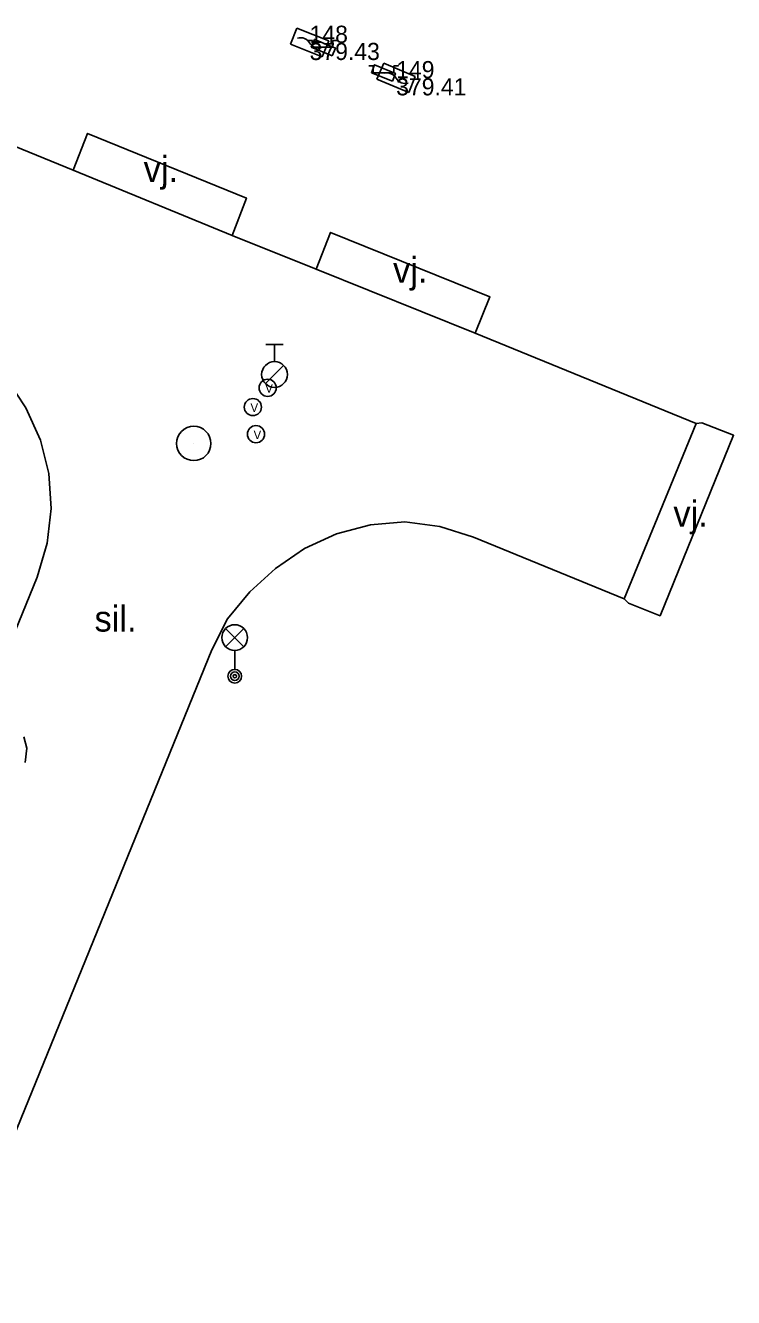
# Model space of a CAD drawing. Extents: x -836568 to -836015, y -1070547 to -1070212.
# Drawn here: x -836394 to -836373.39, y -1070376.08 to -1070339.02 of the extents above; entities that cross this region are included whole.
import ezdxf

# ---------------------------------------------------------------- set-up
doc = ezdxf.new("R2010")
doc.units = 0
for name, color, linetype in [('BodPole_mer', 7, 'Continuous'), ('BodPole_popis', 7, 'Continuous'), ('Doprava_hranice', 7, 'Continuous'), ('Doprava_kody', 7, 'Continuous'), ('PovrZnIS_body', 7, 'Continuous'), ('PovrZnIS_hranice', 7, 'Continuous'), ('PovrZnIS_kody', 7, 'Continuous')]:
    doc.layers.add(name, color=color, linetype=linetype)

msp = doc.modelspace()

# ---------------------------------------------------------------- linework, layer by layer
at = {"layer": 'BodPole_mer'}
for p, q in [((-836385.73, -1070339.53), (-836385.73, -1070339.53)), ((-836385.59, -1070339.43), (-836385.59, -1070339.43)), ((-836385.59, -1070339.43), (-836385.59, -1070339.43)), ((-836385.68, -1070339.66), (-836385.68, -1070339.66)), ((-836385.68, -1070339.66), (-836385.68, -1070339.66)), ((-836385.07, -1070339.91), (-836385.07, -1070339.91)), ((-836385.07, -1070339.91), (-836385.07, -1070339.91)), ((-836384.98, -1070339.68), (-836384.98, -1070339.68)), ((-836384.98, -1070339.68), (-836384.98, -1070339.68)), ((-836383.84, -1070340.17), (-836383.84, -1070340.17)), ((-836383.84, -1070340.17), (-836383.84, -1070340.17)), ((-836383.93, -1070340.4), (-836383.93, -1070340.4)), ((-836383.93, -1070340.4), (-836383.93, -1070340.4)), ((-836383.32, -1070340.65), (-836383.32, -1070340.65)), ((-836383.32, -1070340.65), (-836383.32, -1070340.65)), ((-836383.23, -1070340.42), (-836383.23, -1070340.42)), ((-836383.23, -1070340.42), (-836383.23, -1070340.42)), ((-836383.21, -1070340.56), (-836383.21, -1070340.56)), ((-836392.19, -1070342.17), (-836392.19, -1070342.17)), ((-836392.61, -1070343.24), (-836392.61, -1070343.24)), ((-836387.57, -1070344.05), (-836387.57, -1070344.05)), ((-836387.98, -1070345.14), (-836387.98, -1070345.14)), ((-836385.12, -1070345.05), (-836385.12, -1070345.05)), ((-836385.54, -1070346.12), (-836385.54, -1070346.12)), ((-836380.48, -1070346.93), (-836380.48, -1070346.93)), ((-836380.91, -1070347.99), (-836380.91, -1070347.99)), ((-836386.75, -1070349.19), (-836386.75, -1070349.19)), ((-836386.95, -1070349.58), (-836386.95, -1070349.58)), ((-836393.99, -1070350.16), (-836393.99, -1070350.16)), ((-836387.38, -1070350.14), (-836387.38, -1070350.14)), ((-836374.48, -1070350.62), (-836374.48, -1070350.62)), ((-836374.31, -1070350.6), (-836374.31, -1070350.6)), ((-836393.56, -1070351.1), (-836393.56, -1070351.1)), ((-836387.29, -1070350.93), (-836387.29, -1070350.93)), ((-836373.39, -1070350.96), (-836373.39, -1070350.96)), ((-836389.1, -1070351.2), (-836389.1, -1070351.2)), ((-836393.32, -1070352.07), (-836393.32, -1070352.07)), ((-836393.25, -1070353.09), (-836393.25, -1070353.09)), ((-836383.96, -1070353.57), (-836383.96, -1070353.57)), ((-836382.96, -1070353.48), (-836382.96, -1070353.48)), ((-836381.94, -1070353.62), (-836381.94, -1070353.62)), ((-836393.37, -1070354.1), (-836393.37, -1070354.1)), ((-836384.95, -1070353.83), (-836384.95, -1070353.83)), ((-836380.96, -1070353.93), (-836380.96, -1070353.93)), ((-836385.88, -1070354.26), (-836385.88, -1070354.26)), ((-836386.72, -1070354.84), (-836386.72, -1070354.84)), ((-836393.66, -1070355.09), (-836393.66, -1070355.09)), ((-836387.47, -1070355.52), (-836387.47, -1070355.52)), ((-836376.57, -1070355.73), (-836376.57, -1070355.73)), ((-836376.45, -1070355.85), (-836376.45, -1070355.85)), ((-836388.12, -1070356.31), (-836388.12, -1070356.31)), ((-836375.53, -1070356.22), (-836375.53, -1070356.22)), ((-836388.58, -1070357.21), (-836388.58, -1070357.21)), ((-836387.91, -1070357.98), (-836387.91, -1070357.98)), ((-836393.96, -1070360.08), (-836393.96, -1070360.08))]:
    msp.add_line(p, q, dxfattribs=at)
at = {"layer": 'Doprava_hranice'}
for points in [[(-836399.02, -1070340.62), (-836392.61, -1070343.24), (-836387.98, -1070345.14), (-836385.54, -1070346.12), (-836380.91, -1070347.99), (-836374.48, -1070350.62), (-836376.57, -1070355.73), (-836380.96, -1070353.93), (-836381.94, -1070353.62), (-836382.96, -1070353.48), (-836383.96, -1070353.57), (-836384.95, -1070353.83), (-836385.88, -1070354.26), (-836386.72, -1070354.84), (-836387.47, -1070355.52), (-836388.12, -1070356.31), (-836388.58, -1070357.21), (-836396.26, -1070376.08)], [(-836392.61, -1070343.24), (-836392.19, -1070342.17), (-836387.57, -1070344.05), (-836387.98, -1070345.14)], [(-836385.54, -1070346.12), (-836385.12, -1070345.05), (-836380.48, -1070346.93), (-836380.91, -1070347.99)], [(-836395.25, -1070358.98), (-836393.66, -1070355.09), (-836393.37, -1070354.1), (-836393.25, -1070353.09), (-836393.32, -1070352.07), (-836393.56, -1070351.1), (-836393.99, -1070350.16), (-836394.55, -1070349.31)], [(-836374.48, -1070350.62), (-836374.31, -1070350.6), (-836373.39, -1070350.96), (-836375.53, -1070356.22), (-836376.45, -1070355.85), (-836376.57, -1070355.73)], [(-836394.01, -1070360.49), (-836393.96, -1070360.08), (-836394.05, -1070359.75)]]:
    msp.add_lwpolyline(points, dxfattribs=at)
at = {"layer": 'PovrZnIS_body'}
for p, q in [((-836386.287, -1070339.564), (-836386.102, -1070339.099)), ((-836386.102, -1070339.099), (-836385.173, -1070339.471)), ((-836385.359, -1070339.935), (-836386.287, -1070339.564)), ((-836385.173, -1070339.471), (-836385.359, -1070339.935)), ((-836383.768, -1070340.583), (-836383.573, -1070340.122)), ((-836383.573, -1070340.122), (-836382.652, -1070340.511)), ((-836382.846, -1070340.972), (-836383.768, -1070340.583)), ((-836382.652, -1070340.511), (-836382.846, -1070340.972)), ((-836387, -1070348.315), (-836386.5, -1070348.315)), ((-836386.75, -1070348.315), (-836386.75, -1070348.815)), ((-836386.485, -1070348.925), (-836387.015, -1070349.455)), ((-836388.175, -1070357.12), (-836387.645, -1070356.59)), ((-836388.175, -1070356.59), (-836387.645, -1070357.12)), ((-836387.91, -1070357.78), (-836387.91, -1070357.23))]:
    msp.add_line(p, q, dxfattribs=at)
for points in [[(-836386.08, -1070339.39), (-836386.032, -1070339.381), (-836385.982, -1070339.38), (-836385.931, -1070339.387), (-836385.882, -1070339.402), (-836385.835, -1070339.425), (-836385.793, -1070339.455), (-836385.758, -1070339.491), (-836385.73, -1070339.53)], [(-836385.73, -1070339.53), (-836385.702, -1070339.569), (-836385.667, -1070339.604), (-836385.626, -1070339.634), (-836385.579, -1070339.658), (-836385.529, -1070339.673), (-836385.479, -1070339.68), (-836385.429, -1070339.678), (-836385.382, -1070339.669)], [(-836383.557, -1070340.413), (-836383.509, -1070340.406), (-836383.459, -1070340.405), (-836383.409, -1070340.413), (-836383.359, -1070340.429), (-836383.313, -1070340.453), (-836383.272, -1070340.484), (-836383.237, -1070340.52), (-836383.21, -1070340.56)], [(-836383.21, -1070340.56), (-836383.183, -1070340.599), (-836383.148, -1070340.636), (-836383.108, -1070340.666), (-836383.062, -1070340.69), (-836383.012, -1070340.707), (-836382.962, -1070340.714), (-836382.912, -1070340.714), (-836382.864, -1070340.706)]]:
    msp.add_lwpolyline(points, dxfattribs=at)
for centre, radius in [((-836386.75, -1070349.19), 0.375), ((-836386.95, -1070349.58), 0.25), ((-836387.38, -1070350.14), 0.25), ((-836389.1, -1070351.2), 0.5), ((-836387.29, -1070350.93), 0.25)]:
    msp.add_circle(centre, radius, dxfattribs=at)
for centre, major_axis in [((-836387.91, -1070356.855), (0.375, 0)), ((-836387.91, -1070357.98), (0.2, 0)), ((-836387.906, -1070357.98), (0.125, 0)), ((-836387.906, -1070357.98), (0.05, 0))]:
    msp.add_ellipse(centre, major_axis=major_axis, ratio=0.999998, dxfattribs=at)
at = {"layer": 'PovrZnIS_hranice'}
for p, q in [((-836385.68, -1070339.66), (-836385.07, -1070339.91)), ((-836385.68, -1070339.66), (-836385.07, -1070339.91)), ((-836383.93, -1070340.4), (-836383.32, -1070340.65)), ((-836383.93, -1070340.4), (-836383.32, -1070340.65))]:
    msp.add_line(p, q, dxfattribs=at)
for points in [[(-836385.68, -1070339.66), (-836385.59, -1070339.43), (-836384.98, -1070339.68), (-836385.07, -1070339.91)], [(-836385.68, -1070339.66), (-836385.59, -1070339.43), (-836384.98, -1070339.68), (-836385.07, -1070339.91)], [(-836383.93, -1070340.4), (-836383.84, -1070340.17), (-836383.23, -1070340.42), (-836383.32, -1070340.65)], [(-836383.93, -1070340.4), (-836383.84, -1070340.17), (-836383.23, -1070340.42), (-836383.32, -1070340.65)]]:
    msp.add_lwpolyline(points, dxfattribs=at)
at = {"layer": 'PovrZnIS_kody'}
for p, q in [((-836385.771, -1070339.46), (-836385.65, -1070339.46)), ((-836385.771, -1070339.46), (-836385.65, -1070339.46)), ((-836385.65, -1070339.46), (-836385.65, -1070339.66)), ((-836385.65, -1070339.46), (-836385.65, -1070339.66)), ((-836385.05, -1070339.66), (-836385.05, -1070339.46)), ((-836385.05, -1070339.46), (-836384.916, -1070339.46)), ((-836385.05, -1070339.66), (-836385.05, -1070339.46)), ((-836385.05, -1070339.46), (-836384.916, -1070339.46)), ((-836385.65, -1070339.66), (-836385.05, -1070339.66)), ((-836385.65, -1070339.66), (-836385.05, -1070339.66)), ((-836384.001, -1070340.2), (-836383.88, -1070340.2)), ((-836384.001, -1070340.2), (-836383.88, -1070340.2)), ((-836383.88, -1070340.2), (-836383.88, -1070340.4)), ((-836383.88, -1070340.2), (-836383.88, -1070340.4)), ((-836383.28, -1070340.4), (-836383.28, -1070340.2)), ((-836383.28, -1070340.2), (-836383.146, -1070340.2)), ((-836383.28, -1070340.4), (-836383.28, -1070340.2)), ((-836383.28, -1070340.2), (-836383.146, -1070340.2)), ((-836383.88, -1070340.4), (-836383.28, -1070340.4)), ((-836383.88, -1070340.4), (-836383.28, -1070340.4))]:
    msp.add_line(p, q, dxfattribs=at)

# ---------------------------------------------------------------- texts
at = {"layer": 'BodPole_popis'}
for s, p in [('148', (-836385.73, -1070339.53)), ('379.43', (-836385.73, -1070340.03)), ('149', (-836383.21, -1070340.56)), ('379.41', (-836383.21, -1070341.06))]:
    msp.add_text(s, height=0.5, dxfattribs=at).set_placement(p)
at = {"layer": 'Doprava_kody'}
for s, p in [('vj.', (-836390.56, -1070343.58)), ('vj.', (-836383.3, -1070346.52)), ('vj.', (-836375.14, -1070353.62)), ('sil.', (-836391.99, -1070356.68))]:
    msp.add_text(s, height=0.75, dxfattribs=at).set_placement(p)
at = {"layer": 'PovrZnIS_body'}
for p in [(-836387.021, -1070349.723), (-836387.451, -1070350.283), (-836387.361, -1070351.073)]:
    msp.add_text('V', height=0.25, dxfattribs=at).set_placement(p)

doc.saveas('drawing.dxf')
